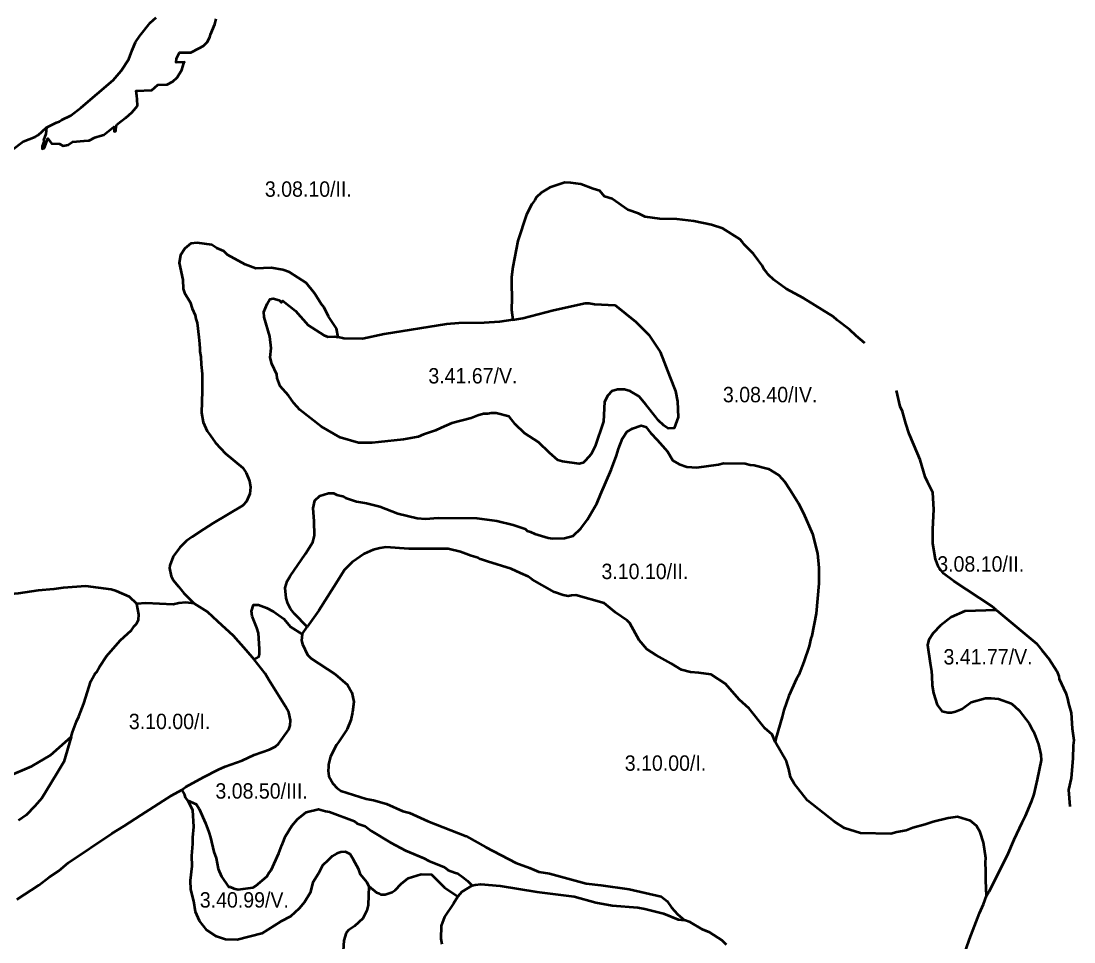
# Model space of a CAD drawing. Extents: x -555506 to -553028, y -1186750 to -1182668.
# Drawn here: x -554397 to -553028, y -1185749 to -1184553 of the extents above; entities that cross this region are included whole.
import ezdxf
from ezdxf.enums import TextEntityAlignment as Align

# ---------------------------------------------------------------- set-up
doc = ezdxf.new("R2010")
doc.units = 0
doc.header["$LTSCALE"] = 8
doc.layers.add('21', color=7, linetype='Continuous', lineweight=53)
doc.layers.add('22', color=7, linetype='Continuous')

msp = doc.modelspace()

# ---------------------------------------------------------------- linework, layer by layer
at = {"layer": '21'}
msp.add_line((-554031.625, -1185349.376), (-554025.25, -1185339.625), dxfattribs=at)
for points in [[(-554364, -1184690.875), (-554364.875, -1184699.375), (-554367.95, -1184707.27), (-554367.35, -1184708.341), (-554368.47, -1184711.54), (-554369.736, -1184715.158), (-554369.94, -1184718.501), (-554366.54, -1184717.58), (-554362.22, -1184705.441), (-554357.64, -1184711.841), (-554347.4, -1184712.36), (-554342.58, -1184714.801), (-554335.95, -1184713.64), (-554330.24, -1184709.56), (-554315.2, -1184708.27), (-554309.96, -1184707.891), (-554308.51, -1184707.781), (-554301.21, -1184704.05), (-554299.98, -1184703.66), (-554294.55, -1184701.98), (-554289.4, -1184700.39), (-554285.24, -1184697.051), (-554276.41, -1184689.961), (-554276.06, -1184696.299), (-554274.562, -1184695.501), (-554273.83, -1184695.06), (-554273.94, -1184693.191), (-554273.25, -1184687.46), (-554267.01, -1184682.661), (-554261.49, -1184678.421), (-554260.66, -1184677.771), (-554253.15, -1184671.501), (-554250.511, -1184668.307), (-554245.93, -1184662.761), (-554246.31, -1184654.171), (-554246.78, -1184649.631), (-554247.47, -1184643.351), (-554226.98, -1184642.35), (-554219.51, -1184635.3), (-554207.3, -1184635.19), (-554199.937, -1184631.125), (-554194.375, -1184626.001), (-554188.062, -1184615.876), (-554185.5, -1184607.376), (-554184.547, -1184606.21), (-554195.61, -1184606.4), (-554195.16, -1184601.301), (-554191.34, -1184593.33), (-554176.53, -1184593.57), (-554165.66, -1184587.761), (-554159.8, -1184584.631), (-554155, -1184580.25), (-554151.562, -1184573.501), (-554150.75, -1184570.001), (-554145.25, -1184556.501), (-554143.5, -1184549.751)], [(-554364, -1184690.875), (-554350.991, -1184684.397), (-554347.38, -1184683.02), (-554344.41, -1184681.421), (-554344.37, -1184681.101), (-554332.625, -1184675.251), (-554319.062, -1184665), (-554277.5, -1184629.375), (-554266.875, -1184617.501), (-554257.125, -1184602.251), (-554252.937, -1184590.375), (-554248.25, -1184580.25), (-554242.75, -1184571.75), (-554229.187, -1184554.75), (-554221.562, -1184548)], [(-554626.875, -1184837.125), (-554611.625, -1184835.875), (-554606.062, -1184833.375), (-554566.625, -1184818.5), (-554542.5, -1184810.5), (-554469.562, -1184779.501), (-554447.937, -1184767.251), (-554440.75, -1184760.375), (-554435.25, -1184755.375), (-554424.625, -1184743.501), (-554421.625, -1184736.626), (-554416.125, -1184728.251), (-554408.937, -1184719.751), (-554394.5, -1184709.126), (-554378.812, -1184703.125), (-554375, -1184701), (-554364, -1184690.875)], [(-553300.104, -1184971.065), (-553311.25, -1184961.751), (-553319.75, -1184953.375), (-553335.875, -1184941.501), (-553341.375, -1184936.376), (-553379.937, -1184912.626), (-553402.437, -1184900.751), (-553418.5, -1184888.875), (-553425.75, -1184882.125), (-553427.875, -1184878.75), (-553430.812, -1184875.25), (-553433.375, -1184870.25), (-553438.875, -1184863.5), (-553444.812, -1184855), (-553456.687, -1184843.126), (-553459.25, -1184839.751), (-553462.625, -1184836.251), (-553484.687, -1184822.376), (-553499.5, -1184817.251), (-553522.375, -1184812.501), (-553544.437, -1184810), (-553566.5, -1184809.626), (-553585.562, -1184807), (-553594.5, -1184802.75), (-553608.062, -1184798.126), (-553628.375, -1184783.751), (-553638.562, -1184780.751), (-553644.5, -1184773.126), (-553653.437, -1184770.626), (-553669.125, -1184764.625), (-553682.25, -1184763.001), (-553690.312, -1184762.5), (-553709.812, -1184768.876), (-553720.375, -1184775.251), (-553727.187, -1184782), (-553729.312, -1184785.376), (-553733.125, -1184790.5), (-553739.875, -1184804.125), (-553751.375, -1184838), (-553757.687, -1184871.876), (-553759.375, -1184885.501), (-553759.375, -1184894.001), (-553759, -1184912.626), (-553759.375, -1184927.876), (-553757.75, -1184940.876)], [(-553985, -1184963.5), (-553987.062, -1184952), (-553997.25, -1184936.75), (-554003.187, -1184924.875), (-554007, -1184919.876), (-554015.5, -1184906.251), (-554026.5, -1184892.751), (-554048.125, -1184878.75), (-554056.625, -1184875.75), (-554071.875, -1184873.251), (-554091.812, -1184874.001), (-554105.812, -1184869.001), (-554128.687, -1184856.251), (-554133.375, -1184851.626), (-554142.687, -1184847.75), (-554149.062, -1184843.5), (-554168.125, -1184841.001), (-554176.625, -1184841.876), (-554184.25, -1184848.125), (-554189.75, -1184856.625), (-554191.437, -1184866.876), (-554186.75, -1184888.875), (-554186.375, -1184900.751), (-554184.625, -1184905.875), (-554177.437, -1184917.751), (-554174.5, -1184926.251), (-554170.687, -1184934.625), (-554169.812, -1184939.75), (-554168.125, -1184944.876), (-554166, -1184963.5), (-554165.125, -1184972), (-554164.75, -1184978.751), (-554164.75, -1184982.125), (-554163.437, -1184989), (-554163, -1184999.125), (-554161.75, -1185011.001), (-554161.75, -1185033), (-554162.625, -1185061.876), (-554160.5, -1185073.75), (-554155, -1185085.626), (-554151.187, -1185090.751), (-554144.375, -1185100.876), (-554131.25, -1185114.376), (-554108.75, -1185133.125), (-554104.5, -1185139.875), (-554100.25, -1185150), (-554099, -1185158.5), (-554099.875, -1185167), (-554104.125, -1185177.125), (-554108.75, -1185182.25), (-554147.312, -1185205.125), (-554159.625, -1185212.751), (-554174.5, -1185223), (-554182.125, -1185228), (-554190.562, -1185236.501), (-554199.5, -1185248.376), (-554203.75, -1185260.25), (-554204.125, -1185263.626), (-554202.062, -1185273.875), (-554199.5, -1185279), (-554192.312, -1185287.376), (-554185.5, -1185295.876), (-554171.937, -1185309.501)], [(-553757.75, -1184940.876), (-553744.562, -1184938.875), (-553704.687, -1184928.25), (-553663.562, -1184919.376), (-553658.5, -1184919.376), (-553651.687, -1184920.626), (-553624.562, -1184922.001), (-553597.875, -1184943.626), (-553580.937, -1184960.5), (-553566.062, -1184982.625), (-553553.75, -1185014.751), (-553546.125, -1185033.5), (-553543.625, -1185047.001), (-553542.75, -1185067.375), (-553547.812, -1185081.75), (-553555.875, -1185082.25), (-553561.375, -1185078), (-553568.625, -1185071.251), (-553571.187, -1185067.751), (-553584.75, -1185050.875), (-553593.625, -1185040.626), (-553605.062, -1185033.5), (-553612.687, -1185031.375), (-553621.625, -1185031.375), (-553628.812, -1185033.5), (-553634.312, -1185039.001), (-553638.562, -1185047.501), (-553639.812, -1185072.876), (-553650.875, -1185105.126), (-553655.937, -1185115.251), (-553663.187, -1185123.751), (-553666.125, -1185126.75), (-553671.625, -1185128.001), (-553693.25, -1185125.001), (-553699.187, -1185123.375), (-553710.25, -1185113.626), (-553724.187, -1185100.001), (-553742.437, -1185088.125), (-553754.75, -1185076.251), (-553762.375, -1185066.501), (-553779.312, -1185062.25), (-553785.687, -1185062.25), (-553790.375, -1185063.125), (-553795.875, -1185063.125), (-553803.062, -1185065.25), (-553812, -1185068.626), (-553837, -1185075.001), (-553851, -1185081), (-553858.187, -1185084.75), (-553873.875, -1185089.876), (-553880.687, -1185092.75), (-553899.75, -1185096.251), (-553932.375, -1185099.625), (-553940.437, -1185100.876), (-553958.25, -1185100.501), (-553982.437, -1185093.626), (-554007, -1185079.625), (-554034.562, -1185057.626), (-554042.625, -1185049.126), (-554049.375, -1185039.001), (-554060.437, -1185027.125), (-554064.25, -1185016.876), (-554064.687, -1185011.876), (-554071, -1184998.251), (-554073.125, -1184989.751), (-554071.875, -1184977.875), (-554073.562, -1184962.625), (-554081.187, -1184937.251), (-554081.625, -1184930.375), (-554077.375, -1184920.25), (-554073.562, -1184913.875), (-554069.312, -1184913.001), (-554061.687, -1184915.126), (-554058.75, -1184918.501), (-554056.625, -1184916), (-554040.5, -1184929.125), (-554023.937, -1184947.75), (-554003.625, -1184961), (-553998.5, -1184963.125), (-553989.187, -1184962.625), (-553985, -1184963.5)], [(-553757.75, -1184940.876), (-553775.062, -1184943.626), (-553795, -1184944.876), (-553828.062, -1184945.251), (-553844.187, -1184946.501), (-553925.187, -1184959.626), (-553953.187, -1184965.625), (-553977.312, -1184965.251), (-553985, -1184963.5)], [(-553128.937, -1185318.001), (-553134.875, -1185312.876), (-553184.062, -1185280.626), (-553197.625, -1185270.501), (-553204, -1185262.001), (-553208.25, -1185251.75), (-553211.625, -1185231.5), (-553211.625, -1185212.751), (-553210.375, -1185187.376), (-553211.625, -1185165.251), (-553218.437, -1185151.376), (-553221.375, -1185145.001), (-553228.187, -1185122.876), (-553231.562, -1185114.376), (-553242.125, -1185089), (-553246.812, -1185075.375), (-553251.062, -1185060.125), (-553254, -1185053.376), (-553258.834, -1185032.885)], [(-554025.25, -1185339.625), (-554041.75, -1185323.001), (-554046.875, -1185316.25), (-554050.25, -1185309.501), (-554052.375, -1185302.625), (-554053.625, -1185289.126), (-554051.125, -1185280.626), (-554047.312, -1185273.875), (-554027.375, -1185245.001), (-554018, -1185229.751), (-554015.5, -1185221.251), (-554015.937, -1185202.626), (-554017.187, -1185185.625), (-554015.062, -1185175.5), (-554008.687, -1185169.501), (-553997.25, -1185166.126), (-553990.875, -1185166.126), (-553986.625, -1185168.251), (-553979.437, -1185170), (-553975.187, -1185172.125), (-553961.187, -1185176.751), (-553948.062, -1185179.25), (-553930.687, -1185183.5), (-553907.375, -1185192.501), (-553881.937, -1185198.75), (-553871.312, -1185199.25), (-553854.812, -1185198), (-553804.75, -1185198.75), (-553778.5, -1185202.25), (-553757.312, -1185207.25), (-553741.625, -1185212.375), (-553739.062, -1185214.876), (-553734.812, -1185216.251), (-553729.312, -1185219.126), (-553711.937, -1185224.25), (-553706.375, -1185225.125), (-553690.75, -1185224.625), (-553679.25, -1185221.751), (-553669.5, -1185212), (-553660.625, -1185200.125), (-553648.312, -1185179.75), (-553643.687, -1185167.875), (-553630.062, -1185135.625), (-553622.875, -1185117), (-553620.312, -1185108.501), (-553615.25, -1185094.875), (-553609.312, -1185086.5), (-553602.125, -1185082.25), (-553590.687, -1185078.376), (-553584.75, -1185080.125), (-553578.375, -1185088.125), (-553569.875, -1185096.625), (-553559.687, -1185108.501), (-553556.75, -1185111.875), (-553549.562, -1185123.751), (-553541.5, -1185128.375), (-553531.312, -1185131.875), (-553518.562, -1185132.625), (-553490.187, -1185128.875), (-553483.812, -1185127.126), (-553455.812, -1185127.625), (-553449.062, -1185129.25), (-553443.937, -1185129.75), (-553425.312, -1185134.376), (-553411.75, -1185142.876), (-553404.125, -1185151.376), (-553397.312, -1185161.501), (-553386.75, -1185178.5), (-553379.937, -1185192.001), (-553368.062, -1185219.126), (-553361.687, -1185244.626), (-553360, -1185263.25), (-553359.625, -1185283.626), (-553363.437, -1185322.625), (-553368.937, -1185351.501), (-553370.187, -1185354.875), (-553372.312, -1185365), (-553379.125, -1185385.376), (-553385.875, -1185402.376), (-553388.875, -1185407.375), (-553399, -1185429.5), (-553405.375, -1185448.125), (-553407.5, -1185456.625), (-553415.562, -1185485.001), (-553416.375, -1185489.251)], [(-553416.375, -1185489.251), (-553420.625, -1185479.875), (-553430, -1185471.376), (-553450.312, -1185446), (-553463.5, -1185434.126), (-553481.25, -1185413.75), (-553499.937, -1185401.876), (-553516.062, -1185399.375), (-553526.625, -1185398.875), (-553538.5, -1185395.501), (-553551.625, -1185387.501), (-553571.187, -1185376.5), (-553583.437, -1185368.876), (-553593.625, -1185357), (-553605.5, -1185334.875), (-553608.875, -1185331.501), (-553624.125, -1185321.376), (-553639, -1185309), (-553675.875, -1185298.501), (-553681.375, -1185298.875), (-553685.625, -1185299.75), (-553692.437, -1185298.501), (-553703.437, -1185294.625), (-553732.687, -1185278.501), (-553737.75, -1185274.251), (-553747.562, -1185270.001), (-553759.812, -1185264.5), (-553790.75, -1185254.75), (-553799.687, -1185251.75), (-553802.625, -1185250.125), (-553812, -1185247.5), (-553825.562, -1185242.5), (-553841.625, -1185238.626), (-553892.937, -1185238.251), (-553923.062, -1185236.126), (-553930.687, -1185237.375), (-553939.187, -1185239.876), (-553951.062, -1185245.001), (-553966.75, -1185255.626), (-553976.5, -1185265.751), (-553990.5, -1185287.876), (-554010, -1185318.375), (-554025.25, -1185339.625)], [(-554246.562, -1185309.875), (-554256.312, -1185301), (-554273.25, -1185293.375), (-554280.062, -1185291.25), (-554313.125, -1185287.001), (-554342.375, -1185289.126), (-554354.687, -1185290.751), (-554375, -1185292.5), (-554400.875, -1185296.376), (-554415.312, -1185297.625), (-554442, -1185304), (-554461.062, -1185304.75), (-554471.687, -1185306.875)], [(-554332.187, -1185482.876), (-554330.5, -1185476.501), (-554325, -1185463), (-554322, -1185456.125), (-554315.687, -1185439.251), (-554306.312, -1185410.376), (-554302.125, -1185402.751), (-554300.812, -1185400.251), (-554299.125, -1185398.501), (-554295.312, -1185391.751), (-554286, -1185378.126), (-554268.187, -1185357.75), (-554253.75, -1185344.25), (-554249.937, -1185339.125), (-554247, -1185335.75), (-554244.437, -1185330.625), (-554244, -1185323.876), (-554246.562, -1185309.875)], [(-554171.937, -1185309.501), (-554182.937, -1185308.25), (-554191.875, -1185309), (-554199.5, -1185310.751), (-554235.125, -1185309), (-554246.562, -1185309.875)], [(-554171.937, -1185309.501), (-554154.562, -1185320.5), (-554141.812, -1185332.376), (-554121.5, -1185351.001), (-554104.937, -1185369.626), (-554093.937, -1185382.375)], [(-554093.937, -1185382.375), (-554088, -1185379.001), (-554087.125, -1185375.125), (-554087.125, -1185368.376), (-554088.437, -1185348), (-554090.5, -1185341.25), (-554096.875, -1185326.001), (-554097.75, -1185319.251), (-554094.75, -1185311.125), (-554088.437, -1185311.125), (-554078.25, -1185315.001), (-554068.875, -1185320), (-554055.312, -1185329.376), (-554046.875, -1185339.625), (-554031.625, -1185349.376)], [(-553128.937, -1185318.001), (-553170.062, -1185319.626), (-553187.875, -1185327.251), (-553201.437, -1185337.875), (-553211.187, -1185348), (-553216.687, -1185356.5), (-553218.437, -1185363.251), (-553215, -1185387.001), (-553213.312, -1185397.25), (-553212.875, -1185404.001), (-553212.5, -1185415.875), (-553210.75, -1185426), (-553206.125, -1185441.376), (-553199.75, -1185449.376), (-553192.125, -1185451.126), (-553187.437, -1185451.126), (-553181.937, -1185449.75), (-553173.437, -1185446.376), (-553161.625, -1185437.5), (-553142.937, -1185432.375), (-553135.75, -1185432.375), (-553126, -1185433.25), (-553109.437, -1185439.625), (-553099.25, -1185448.501), (-553086.125, -1185465.5), (-553082.75, -1185472.251), (-553080.625, -1185475.625), (-553078.062, -1185482.5), (-553074.25, -1185492.625), (-553071.312, -1185506.25), (-553070.875, -1185513.001), (-553075.937, -1185538.376), (-553080.187, -1185557.125), (-553083.562, -1185567.25), (-553091.625, -1185585.875), (-553095.875, -1185594.375), (-553106.062, -1185616.376), (-553114.937, -1185636.75), (-553138.687, -1185684.25), (-553141.687, -1185689.376)], [(-553128.937, -1185318.001), (-553076.812, -1185361.626), (-553069.625, -1185370.126), (-553060.25, -1185382), (-553050.5, -1185397.25), (-553047.562, -1185404.001), (-553047.125, -1185407.375), (-553038.625, -1185426), (-553036.5, -1185432.876), (-553035.25, -1185439.625), (-553031.875, -1185451.501), (-553030.187, -1185471.875), (-553028.062, -1185487.126), (-553028.875, -1185493.876), (-553029.312, -1185510.876), (-553031.875, -1185536.251), (-553035.25, -1185551.5), (-553033.544, -1185573.41)], [(-554031.625, -1185349.376), (-554032.437, -1185357.376), (-554031.187, -1185362.501), (-554024.812, -1185376.001), (-554020.125, -1185381.126), (-553988.75, -1185401.5), (-553972.687, -1185415.001), (-553967.125, -1185425.25), (-553964.625, -1185437.126), (-553966.312, -1185450.626), (-553968.437, -1185460.875), (-553973.062, -1185472.751), (-553984.562, -1185489.626), (-553987.062, -1185493.001), (-553994.687, -1185508.251), (-553997.25, -1185518.5), (-553997.25, -1185521.875), (-553997.687, -1185527), (-553996.812, -1185533.751), (-553991.312, -1185543.876), (-553986.625, -1185549.001), (-553981.562, -1185552.875), (-553948.5, -1185563.376), (-553938.75, -1185565.125), (-553921.812, -1185569.751), (-553900.562, -1185579.126), (-553892.125, -1185581.625), (-553868.375, -1185592.25), (-553818.312, -1185611.75), (-553792.875, -1185626.125), (-553753.875, -1185646.501), (-553736.062, -1185652.876), (-553723.812, -1185658.375), (-553710.25, -1185660.5), (-553662.312, -1185673.25), (-553643.25, -1185675.375), (-553606.375, -1185680.5), (-553564.812, -1185690.251), (-553557.187, -1185696.126), (-553551.25, -1185704.626), (-553543.625, -1185713.126), (-553534.687, -1185721.126)], [(-554188.062, -1185551.5), (-554182.937, -1185547.75), (-554160.062, -1185535), (-554140.562, -1185525.251), (-554131.625, -1185521.501), (-554109.625, -1185513.375), (-554093.937, -1185506.25), (-554074, -1185499), (-554066.375, -1185495.126), (-554062.562, -1185491.751), (-554049, -1185473.125), (-554047.312, -1185468.001), (-554046.875, -1185461.25), (-554049, -1185451.126), (-554053.25, -1185443.501), (-554074.812, -1185408.626), (-554079.937, -1185400.251), (-554093.937, -1185382.375)], [(-554668.812, -1185666.001), (-554639.125, -1185660.5), (-554632.375, -1185658.001), (-554627.312, -1185654.125), (-554620.062, -1185645.625), (-554612.437, -1185633.751), (-554606.937, -1185620.25), (-554605.25, -1185610.001), (-554600.562, -1185598.251), (-554592.937, -1185586.375), (-554589.562, -1185582.876), (-554586.187, -1185579.126), (-554572.187, -1185570.251), (-554542.062, -1185560.501), (-554532.312, -1185558.75), (-554434.375, -1185539.626), (-554415.75, -1185534.626), (-554383.062, -1185521.001), (-554358.875, -1185506.626), (-554332.187, -1185482.876)], [(-554332.187, -1185482.876), (-554341.5, -1185515.126), (-554350.875, -1185530.376), (-554364, -1185552.375), (-554370.375, -1185562.626), (-554379.25, -1185572.751), (-554390.687, -1185584.626), (-554400.437, -1185591.376)], [(-553141.687, -1185689.376), (-553142.5, -1185669.376), (-553142.5, -1185657.5), (-553142.937, -1185645.625), (-553142.5, -1185640.626), (-553145.5, -1185620.25), (-553150.125, -1185606.625), (-553154.812, -1185598.251), (-553162.437, -1185591.876), (-553179.375, -1185586.75), (-553191.687, -1185588.5), (-553211.187, -1185593.125), (-553221.375, -1185596.5), (-553237.5, -1185601.125), (-553246.375, -1185604.5), (-553258.25, -1185606.625), (-553266.312, -1185608.75), (-553305.75, -1185608), (-553326.5, -1185601.625), (-553339.687, -1185592.626), (-553374.437, -1185565.501), (-553391.812, -1185543.5), (-553396.5, -1185535), (-553398.625, -1185524.875), (-553402, -1185514.626), (-553416.375, -1185489.251)], [(-554402.562, -1185694), (-554374.187, -1185675.375), (-554360.625, -1185665.126), (-554348.312, -1185656.75), (-554336, -1185646.501), (-554279.187, -1185608.376), (-554263.5, -1185599), (-554241.437, -1185584.626), (-554201.625, -1185559.126), (-554188.062, -1185551.5)], [(-554180.437, -1185565.501), (-554183.375, -1185561.751), (-554184.25, -1185558.376), (-554188.062, -1185551.5)], [(-553945.125, -1185676.626), (-553947.25, -1185672), (-553955.687, -1185661.751), (-553957.812, -1185655.001), (-553965.437, -1185641.501), (-553969.25, -1185635.125), (-553975.187, -1185632.126), (-553981.562, -1185632.5), (-553986.625, -1185634.251), (-553992.562, -1185638.001), (-553997.687, -1185643.125), (-554005.312, -1185649.875), (-554010.375, -1185660.126), (-554017.625, -1185672), (-554021.437, -1185685.5), (-554028.625, -1185697.376), (-554035.437, -1185705.876), (-554046.875, -1185716.001), (-554059.562, -1185722.875), (-554084.187, -1185738.5), (-554116, -1185746.626), (-554131.25, -1185746.126), (-554143.125, -1185742.376), (-554155.812, -1185733.876), (-554165.125, -1185722), (-554170.25, -1185710.126), (-554172.75, -1185696.5), (-554176.625, -1185681.25), (-554177, -1185669.376), (-554174.875, -1185650.751), (-554175.312, -1185637.25), (-554174.062, -1185621.875), (-554174.062, -1185613.501), (-554172.75, -1185599.876), (-554174.062, -1185577.875), (-554180.437, -1185565.501)], [(-554180.437, -1185565.501), (-554169.375, -1185570.251), (-554165.562, -1185576.126), (-554157.5, -1185594.75), (-554152.875, -1185606.625), (-554150.75, -1185613.501), (-554146.5, -1185632.126), (-554143.5, -1185640.626), (-554141, -1185654.125), (-554136.75, -1185664.376), (-554127.437, -1185677.5), (-554125.312, -1185677.875), (-554120.625, -1185679.625), (-554114.687, -1185681.25), (-554095.187, -1185678.375), (-554091.812, -1185676.25), (-554077.812, -1185664.376), (-554074.437, -1185659.251), (-554071.875, -1185655.876), (-554062.125, -1185633.751), (-554058.312, -1185623.626), (-554057.062, -1185621.875), (-554053.25, -1185611.75), (-554045.187, -1185598.251), (-554037.937, -1185589.751), (-554026.5, -1185580.751), (-554010.375, -1185576.626), (-554001.5, -1185579.126), (-553996, -1185580), (-553963.75, -1185592.25), (-553959.937, -1185595.25), (-553949.75, -1185599), (-553942.125, -1185605.001), (-553916.687, -1185620.25), (-553897.187, -1185630.375), (-553873.437, -1185640.626), (-553867.125, -1185644), (-553846.75, -1185652), (-553841.625, -1185655.876), (-553833.625, -1185659.251), (-553829.375, -1185660.5), (-553822.562, -1185665.126), (-553816.625, -1185669.875), (-553810.687, -1185675.75)], [(-553945.125, -1185676.626), (-553934.937, -1185685.126), (-553931.125, -1185686.375), (-553929.437, -1185687.625), (-553923.875, -1185687.625), (-553914.562, -1185684.626), (-553910.75, -1185682.125), (-553903.125, -1185673.626), (-553893.812, -1185666.501), (-553876.875, -1185661), (-553863.687, -1185661.751), (-553846.75, -1185678.375), (-553829.375, -1185690.251)], [(-553945.125, -1185676.626), (-553945.937, -1185701.626), (-553947.625, -1185708.376), (-553952.75, -1185718.625), (-553963.75, -1185728.75), (-553971.375, -1185733.876), (-553974.375, -1185737.25), (-553977.312, -1185747.375), (-553978.625, -1185767.751), (-553981.562, -1185778), (-553985.812, -1185784.751), (-553996.375, -1185796.625), (-554003.187, -1185803.376), (-554008.687, -1185808.875), (-554027.375, -1185814.876), (-554049.375, -1185821.626)], [(-553810.687, -1185675.75), (-553824.25, -1185684.25), (-553829.375, -1185690.251)], [(-553810.687, -1185675.75), (-553806.875, -1185674.875), (-553799.25, -1185674.125), (-553774.25, -1185676.25), (-553726.312, -1185684.25), (-553678, -1185690.251), (-553650, -1185697.876), (-553628.375, -1185702.126), (-553595.312, -1185704.626), (-553586, -1185706.251), (-553561.812, -1185712.25), (-553542.75, -1185720.251), (-553534.687, -1185721.126)], [(-553829.375, -1185690.251), (-553834.875, -1185699.501), (-553846.75, -1185716.5), (-553851, -1185728.375), (-553851.375, -1185745.25), (-553850.125, -1185752.125)], [(-553160.224, -1185907.948), (-553179, -1185926.75), (-553182.812, -1185930.625), (-553189.562, -1185931.5), (-553195.062, -1185930.125), (-553199.75, -1185925.501), (-553204.437, -1185915.376), (-553205.25, -1185908.5), (-553204.437, -1185888.25), (-553198.062, -1185847.5), (-553193.375, -1185827.126), (-553185.75, -1185808.501), (-553181.937, -1185798.25), (-553179.375, -1185788.125), (-553177.312, -1185784.751), (-553163.687, -1185745.75), (-553151, -1185711.875), (-553145.5, -1185700.001), (-553141.687, -1185689.376)], [(-553480, -1185753), (-553485.937, -1185747.001), (-553501.625, -1185736.876), (-553510.937, -1185733), (-553527.062, -1185723.751), (-553534.687, -1185721.126)]]:
    msp.add_lwpolyline(points, dxfattribs=at)

# ---------------------------------------------------------------- texts
at = {"layer": '22', "width": 0.95}
for s, p in [('3.08.10/II.', (-554023.643, -1184780.943)), ('3.41.67/V.', (-553809.64, -1185023.535)), ('3.08.40/IV.', (-553423.078, -1185048.028)), ('3.10.10/II.', (-553585.953, -1185277.744)), ('3.08.10/II.', (-553149.298, -1185268.102)), ('3.41.77/V.', (-553139.784, -1185388.736)), ('3.10.00/I.', (-554204.068, -1185472.737)), ('3.10.00/I.', (-553559.198, -1185526.843)), ('3.08.50/III.', (-554084.432, -1185563.057)), ('3.40.99/V.', (-554106.868, -1185704.629))]:
    msp.add_text(s, height=20, dxfattribs=at).set_placement(p, align=Align.CENTER)

doc.saveas('drawing.dxf')
